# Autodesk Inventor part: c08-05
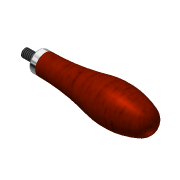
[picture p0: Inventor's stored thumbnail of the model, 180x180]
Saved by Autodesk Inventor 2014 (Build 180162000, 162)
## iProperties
Created: 2010-12
Part Number: c08-05
Document SubType Name: Modeling
Designer: Thom Tremblay
Density: 1 g/cm^3
Material: Generic
Appearance: Generic
Author: Thom Tremblay
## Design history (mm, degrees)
sketch "Sketch1"
  geometry: L1 (93.367, -68.499)-(103.527, -68.499); L2 (103.527, -68.499)-(103.527, -65.324); L3 (103.527, -65.324)-(93.367, -65.324); L4 (93.367, -65.324)-(93.367, -68.499); L5 (103.527, -68.499)-(108.607, -68.499); L6 (108.607, -68.499)-(108.607, -60.879); L7 (108.607, -60.879)-(103.527, -60.879); L8 (103.527, -60.879)-(103.527, -68.499); L9 (192.427, -68.499)-(108.607, -68.499); L10 (192.427, -68.499)-(192.427, -75.403); A1 r 177.8 centre (108.607, 116.921) between (108.607, -60.879) and (149.179, -56.188); A2 r 60.96 centre (163.089, -115.54) between (186.103, -59.091) and (149.179, -56.188); A3 r 10.16 centre (182.267, -68.499) between (192.427, -68.499) and (186.103, -59.091); 1 further point
  constraints: 20 end point, 6 point on circle, 4 parallel, 4 tangent, 3 centre point, 3 perpendicular, 2 horizontal, 1 collinear
  dimensions: "d0" = 10.16 distance of L3.end L2.end; "d1" = 3.175 distance of L2.end L1.end; "d2" = 5.08 distance of L7.end L6.end; "d3" = 7.62 distance of L6.end L5.end; "d4" = 88.9 distance between parallel lines of L10 L2; "d5" = 60.96 radius of A2; "d6" = 177.8 radius of A1; "d7" = 10.16 radius of A3
revolve "Revolution1" sketch "Sketch1" stored, may be unused: angle "d8" = 90 deg
thread "Thread1" dims "d9" = 8.89, "d10" = 0
fillet "Fillet1" dims "d11" = 1.27
body "Solid1"
